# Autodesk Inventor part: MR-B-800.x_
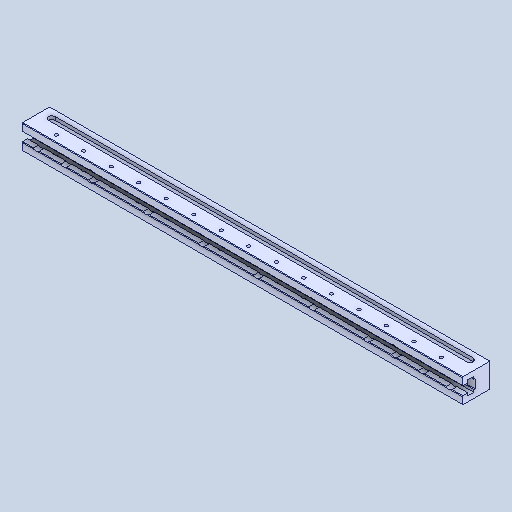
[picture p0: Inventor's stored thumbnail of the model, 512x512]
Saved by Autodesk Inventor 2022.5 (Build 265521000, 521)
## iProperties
Created: 2024-05
Part Number: MR-B-800.x_
Material: 一般
Document SubType Name: Modeling
Designer: ImaoCorp
Density: 1 g/cm^3
Appearance: 既定
Author: ImaoCorp
Sending System: SOLIDWORKS 2022-2022290
MC: AMD64
MC_MODEL: Intel64 Family 6 Model 60 Stepping 3, GenuineIntel
OS: Windows_NT
FRU: Parasolid Version 33.1, build 260,  4-25-2022
FORMAT: text
GUISE: transmit
KEY: FILEMR-B-800.x_t
DATE: Mon May 20 16:29:01 2024
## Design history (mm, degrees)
feature "Base1"
node "ソリッド1"
